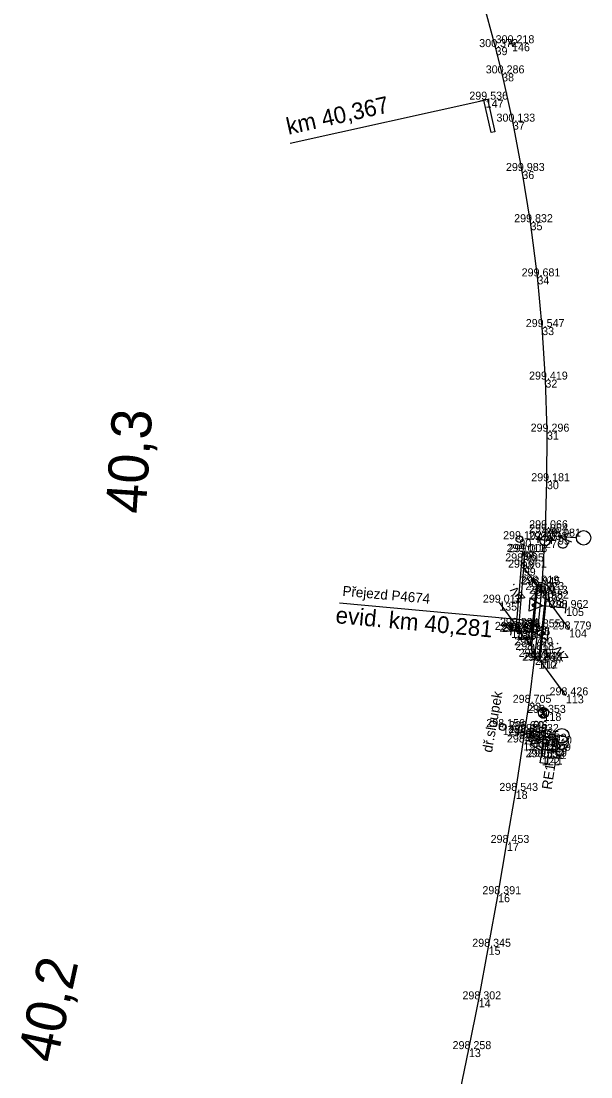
# Model space of a CAD drawing. Extents: x -684938 to -684389, y -1007777 to -1006471.
# Drawn here: x -684554.8 to -684469.4, y -1007124.9 to -1006966.7 of the extents above; entities that cross this region are included whole.
import ezdxf

# ---------------------------------------------------------------- set-up
doc = ezdxf.new("R2010")
doc.units = 0
for name, color, linetype in [('Vrstva 1', 7, 'Continuous'), ('Vrstva 12', 7, 'Continuous'), ('Vrstva 13', 7, 'Continuous'), ('Vrstva 25', 7, 'Continuous'), ('Vrstva 3', 7, 'Continuous'), ('Vrstva 33', 7, 'Continuous'), ('Vrstva 4', 7, 'Continuous'), ('Vrstva 43', 7, 'Continuous'), ('Vrstva 50', 7, 'Continuous'), ('Vrstva 51', 7, 'Continuous'), ('Vrstva 60', 7, 'Continuous'), ('Vrstva 61', 7, 'Continuous'), ('Vrstva 63', 7, 'Continuous'), ('Vrstva 7', 7, 'Continuous'), ('Vrstva 9', 7, 'Continuous')]:
    doc.layers.add(name, color=color, linetype=linetype)

msp = doc.modelspace()

# ---------------------------------------------------------------- linework, layer by layer
at = {"layer": 'Vrstva 1'}
msp.add_lwpolyline([(-684489.29, -1007128.53), (-684487.68, -1007120.78), (-684486.2, -1007113.32), (-684484.73, -1007105.44), (-684483.31, -1007097.56), (-684481.98, -1007089.88), (-684480.67, -1007082.08), (-684479.54, -1007074.82), (-684479.4, -1007073.91), (-684479.32, -1007073.39), (-684479.23, -1007072.83), (-684478.66, -1007068.88), (-684477.78, -1007061.99), (-684477.29, -1007057.57), (-684476.77, -1007051.98), (-684476.28, -1007044.49), (-684476.22, -1007043.32), (-684476.19, -1007042.72), (-684475.99, -1007035.67), (-684475.98, -1007028.24), (-684476.22, -1007020.44), (-684476.71, -1007012.57), (-684477.42, -1007004.97), (-684478.45, -1006996.85), (-684479.68, -1006989.18), (-684481.1, -1006981.78), (-684482.71, -1006974.55), (-684483.69, -1006970.61), (-684485.64, -1006963.4)], dxfattribs=at)
at = {"layer": 'Vrstva 12'}
msp.add_line((-684476.74, -1007077.05), (-684476.39, -1007074.71), dxfattribs=at)
at = {"layer": 'Vrstva 13'}
msp.add_lwpolyline([(-684480.63, -1007058.2), (-684480.27, -1007058.25)], dxfattribs=at)
at = {"layer": 'Vrstva 25'}
for points in [[(-684475.99, -1007078), (-684476.98, -1007077.85), (-684476.67, -1007075.87), (-684475.69, -1007076.03), (-684475.99, -1007078)], [(-684475.4, -1007077.12), (-684476.39, -1007076.97), (-684476.08, -1007074.99), (-684475.09, -1007075.15), (-684475.4, -1007077.12)]]:
    msp.add_lwpolyline(points, dxfattribs=at)
at = {"layer": 'Vrstva 3'}
for p, q in [((-684477.31, -1007044.92), (-684477.24, -1007043.92)), ((-684475.31, -1007045.05), (-684475.24, -1007044.06)), ((-684474.33, -1007043.97), (-684471.58, -1007044.1)), ((-684477.27, -1007044.42), (-684475.28, -1007044.55)), ((-684480.39, -1007073.73), (-684480.24, -1007072.74)), ((-684480.31, -1007073.24), (-684478.33, -1007073.53)), ((-684478.41, -1007074.03), (-684478.26, -1007073.04)), ((-684477.67, -1007074.23), (-684474.94, -1007074.64)), ((-684477.56, -1007073.25), (-684474.83, -1007073.65))]:
    msp.add_line(p, q, dxfattribs=at)
for points in [[(-684472.23, -1007043.37), (-684474.33, -1007043.97), (-684472.3, -1007044.75)], [(-684475.41, -1007072.87), (-684477.56, -1007073.25), (-684475.61, -1007074.23)], [(-684475.52, -1007073.86), (-684477.67, -1007074.23), (-684475.72, -1007075.22)]]:
    msp.add_lwpolyline(points, dxfattribs=at)
for centre in [(-684470.49, -1007044.15), (-684473.75, -1007073.81), (-684473.87, -1007074.81)]:
    msp.add_circle(centre, 1.08, dxfattribs=at)
at = {"layer": 'Vrstva 33'}
for p, q in [((-684476.17, -1007075.48), (-684476.02, -1007074.49)), ((-684476.09, -1007074.99), (-684475.11, -1007075.14))]:
    msp.add_line(p, q, dxfattribs=at)
msp.add_lwpolyline([(-684476.74, -1007075.9), (-684476.44, -1007073.93), (-684474.46, -1007074.22), (-684474.76, -1007076.2), (-684476.74, -1007075.9)], dxfattribs=at)
at = {"layer": 'Vrstva 4'}
for p, q in [((-684507.07, -1007053.89), (-684477.2, -1007056.65)), ((-684477.79, -1007054.44), (-684478.1, -1007054.07)), ((-684473.19, -1007055.45), (-684473.04, -1007053.9)), ((-684481.25, -1007057.18), (-684481.43, -1007058.72)), ((-684476.67, -1007058.26), (-684476.37, -1007058.65))]:
    msp.add_line(p, q, dxfattribs=at)
for points in [[(-684478.28, -1007060.96), (-684477.33, -1007051.23), (-684476.22, -1007052.54), (-684477.26, -1007062.58), (-684478.28, -1007060.96)], [(-684473.12, -1007054.67), (-684476.58, -1007054.35), (-684478.67, -1007055.15), (-684478.49, -1007053.16), (-684476.58, -1007054.35)], [(-684481.34, -1007057.95), (-684477.88, -1007058.33), (-684475.78, -1007057.58), (-684475.99, -1007059.56), (-684477.88, -1007058.33)]]:
    msp.add_lwpolyline(points, dxfattribs=at)
for centre in [(-684477.94, -1007054.25), (-684476.52, -1007058.45)]:
    msp.add_circle(centre, 0.248, dxfattribs=at)
at = {"layer": 'Vrstva 43'}
msp.add_lwpolyline([(-684480.27, -1007058.25), (-684479.46, -1007048.63), (-684479.3, -1007046.31), (-684479.66, -1007046.26), (-684479.78, -1007047.68), (-684480.58, -1007057.36), (-684480.63, -1007058.2), (-684480.27, -1007058.25)], dxfattribs=at)
at = {"layer": 'Vrstva 50'}
msp.add_line((-684482.62, -1007072.46), (-684482.63, -1007072.55), dxfattribs=at)
msp.add_circle((-684482.62, -1007072.51), 0.5, dxfattribs=at)
at = {"layer": 'Vrstva 51'}
for points in [[(-684483.14, -1007053.87), (-684480.58, -1007057.36), (-684480.21, -1007058.09), (-684478.44, -1007060.26), (-684477.49, -1007051.03), (-684479.46, -1007048.63)], [(-684473.15, -1007067.76), (-684477.02, -1007062.52), (-684476.07, -1007053.27), (-684472.68, -1007057.89)]]:
    msp.add_lwpolyline(points, dxfattribs=at)
at = {"layer": 'Vrstva 60'}
for p, q in [((-684481.22, -1006970.03), (-684481.22, -1006970.03)), ((-684483.69, -1006970.61), (-684483.69, -1006970.61)), ((-684482.71, -1006974.55), (-684482.71, -1006974.55)), ((-684485.17, -1006978.49), (-684485.17, -1006978.49)), ((-684481.1, -1006981.78), (-684481.1, -1006981.78)), ((-684479.68, -1006989.18), (-684479.68, -1006989.18)), ((-684478.45, -1006996.85), (-684478.45, -1006996.85)), ((-684477.42, -1007004.97), (-684477.42, -1007004.97)), ((-684476.71, -1007012.57), (-684476.71, -1007012.57)), ((-684476.22, -1007020.44), (-684476.22, -1007020.44)), ((-684475.98, -1007028.24), (-684475.98, -1007028.24)), ((-684475.99, -1007035.67), (-684475.99, -1007035.67)), ((-684476.19, -1007042.72), (-684476.19, -1007042.72)), ((-684480.12, -1007044.36), (-684480.12, -1007044.36)), ((-684476.22, -1007043.32), (-684476.22, -1007043.32)), ((-684474.33, -1007043.97), (-684474.33, -1007043.97)), ((-684476.28, -1007044.49), (-684476.28, -1007044.49)), ((-684479.66, -1007046.26), (-684479.66, -1007046.26)), ((-684479.3, -1007046.31), (-684479.3, -1007046.31)), ((-684479.78, -1007047.68), (-684479.78, -1007047.68)), ((-684479.46, -1007048.63), (-684479.46, -1007048.63)), ((-684477.49, -1007051.03), (-684477.49, -1007051.03)), ((-684477.33, -1007051.23), (-684477.33, -1007051.23)), ((-684476.77, -1007051.98), (-684476.77, -1007051.98)), ((-684483.14, -1007053.87), (-684483.14, -1007053.87)), ((-684476.22, -1007052.54), (-684476.22, -1007052.54)), ((-684476.07, -1007053.27), (-684476.07, -1007053.27)), ((-684473.12, -1007054.67), (-684473.12, -1007054.67)), ((-684481.34, -1007057.95), (-684481.34, -1007057.95)), ((-684480.63, -1007058.2), (-684480.63, -1007058.2)), ((-684480.58, -1007057.36), (-684480.58, -1007057.36)), ((-684480.27, -1007058.25), (-684480.27, -1007058.25)), ((-684480.21, -1007058.09), (-684480.21, -1007058.09)), ((-684477.29, -1007057.57), (-684477.29, -1007057.57)), ((-684472.68, -1007057.89), (-684472.68, -1007057.89)), ((-684478.44, -1007060.26), (-684478.44, -1007060.26)), ((-684478.28, -1007060.96), (-684478.28, -1007060.96)), ((-684477.78, -1007061.99), (-684477.78, -1007061.99)), ((-684477.26, -1007062.58), (-684477.26, -1007062.58)), ((-684477.02, -1007062.52), (-684477.02, -1007062.52)), ((-684473.15, -1007067.76), (-684473.15, -1007067.76)), ((-684478.66, -1007068.88), (-684478.66, -1007068.88)), ((-684476.51, -1007070.39), (-684476.51, -1007070.39)), ((-684482.62, -1007072.51), (-684482.62, -1007072.51)), ((-684479.23, -1007072.83), (-684479.23, -1007072.83)), ((-684479.4, -1007073.91), (-684479.4, -1007073.91)), ((-684479.32, -1007073.39), (-684479.32, -1007073.39)), ((-684477.67, -1007074.23), (-684477.67, -1007074.23)), ((-684477.56, -1007073.25), (-684477.56, -1007073.25)), ((-684479.54, -1007074.82), (-684479.54, -1007074.82)), ((-684476.39, -1007074.71), (-684476.39, -1007074.71)), ((-684475.6, -1007075.06), (-684475.6, -1007075.06)), ((-684476.74, -1007077.05), (-684476.74, -1007077.05)), ((-684476.33, -1007076.94), (-684476.33, -1007076.94)), ((-684475.74, -1007076.06), (-684475.74, -1007076.06)), ((-684480.67, -1007082.08), (-684480.67, -1007082.08)), ((-684481.98, -1007089.88), (-684481.98, -1007089.88)), ((-684483.31, -1007097.56), (-684483.31, -1007097.56)), ((-684484.73, -1007105.44), (-684484.73, -1007105.44)), ((-684486.2, -1007113.32), (-684486.2, -1007113.32)), ((-684487.68, -1007120.78), (-684487.68, -1007120.78))]:
    msp.add_line(p, q, dxfattribs=at)
at = {"layer": 'Vrstva 63'}
for p, q in [((-684476.34, -1007070.26), (-684476.78, -1007069.67)), ((-684476.1, -1007070.08), (-684476.44, -1007069.63)), ((-684477.12, -1007070.84), (-684476.5, -1007070.39)), ((-684476.5, -1007070.39), (-684476.96, -1007069.78)), ((-684476.55, -1007071.15), (-684476.9, -1007070.68)), ((-684476.22, -1007071.1), (-684476.66, -1007070.5)), ((-684475.89, -1007069.93), (-684476.5, -1007070.39)), ((-684476.5, -1007070.39), (-684476.04, -1007071))]:
    msp.add_line(p, q, dxfattribs=at)
msp.add_circle((-684476.5, -1007070.39), 0.764, dxfattribs=at)
for start, end in [(36.8703, 126.7638), (216.4195, 306.7375)]:
    msp.add_arc((-684476.5, -1007070.39), 0.765, start, end, dxfattribs=at)
at = {"layer": 'Vrstva 7'}
for p, q in [((-684481.71, -1006970.15), (-684480.74, -1006969.91)), ((-684481.1, -1006970.51), (-684481.34, -1006969.54)), ((-684480.12, -1007044.41), (-684480.11, -1007044.31))]:
    msp.add_line(p, q, dxfattribs=at)
for centre, radius in [((-684480.12, -1007044.36), 0.5), ((-684476.28, -1007044.61), 0.75)]:
    msp.add_circle(centre, radius, dxfattribs=at)
at = {"layer": 'Vrstva 9'}
msp.add_line((-684514.45, -1006985.02), (-684485.17, -1006978.49), dxfattribs=at)
msp.add_lwpolyline([(-684486.05, -1006978.68), (-684485.46, -1006978.55), (-684484.88, -1006978.42), (-684483.79, -1006983.3), (-684484.37, -1006983.43), (-684485.46, -1006978.55)], dxfattribs=at)

# ---------------------------------------------------------------- texts
at = {"layer": 'Vrstva 25'}
for s, p in [('k.s.', (-684473.61, -1007077.46)), ('RE1', (-684475.3, -1007081.96))]:
    msp.add_text(s, height=1.5, rotation=81.1596, dxfattribs=at).set_placement(p)
at = {"layer": 'Vrstva 3'}
for s, rotation, p in [('C', 87.2947, (-684472.9, -1007045.9)), ('B', 81.817, (-684476.59, -1007072.87)), ('A', 81.512, (-684477.05, -1007076.01))]:
    msp.add_text(s, height=1.5, rotation=rotation, dxfattribs=at).set_placement(p)
at = {"layer": 'Vrstva 4'}
for s, height, p in [('Přejezd P4674', 1.5, (-684506.67, -1007052.83)), ('evid. km 40,281', 2.5, (-684507.74, -1007056.93))]:
    msp.add_text(s, height=height, rotation=354.7233, dxfattribs=at).set_placement(p)
at = {"layer": 'Vrstva 50'}
msp.add_text('dř.sloupek', height=1.5, rotation=80.1558, dxfattribs=at).set_placement((-684484.23, -1007076.41))
at = {"layer": 'Vrstva 51'}
for rotation, p in [(129.3777, (-684479.13, -1007053.2)), (126.4268, (-684472.69, -1007062.13))]:
    msp.add_text('živ.', height=1.5, rotation=rotation, dxfattribs=at).set_placement(p)
at = {"layer": 'Vrstva 60'}
for s, p in [('146', (-684481.22, -1006971.23)), ('39', (-684483.69, -1006971.81)), ('38', (-684482.71, -1006975.75)), ('147', (-684485.17, -1006979.69)), ('37', (-684481.1, -1006982.98)), ('36', (-684479.68, -1006990.38)), ('35', (-684478.45, -1006998.05)), ('34', (-684477.42, -1007006.17)), ('33', (-684476.71, -1007013.77)), ('32', (-684476.22, -1007021.64)), ('31', (-684475.98, -1007029.44)), ('30', (-684475.99, -1007036.86)), ('29', (-684476.19, -1007043.93)), ('90', (-684480.12, -1007045.56)), ('28', (-684476.22, -1007044.52)), ('95', (-684474.33, -1007045.17)), ('27', (-684476.28, -1007045.69)), ('97', (-684479.66, -1007047.46)), ('96', (-684479.3, -1007047.51)), ('98', (-684479.78, -1007048.88)), ('99', (-684479.46, -1007049.83)), ('100', (-684477.49, -1007052.23)), ('101', (-684477.33, -1007052.43)), ('26', (-684476.77, -1007053.18)), ('135', (-684483.14, -1007055.07)), ('102', (-684476.22, -1007053.74)), ('103', (-684476.07, -1007054.47)), ('105', (-684473.12, -1007055.87)), ('131', (-684481.34, -1007059.15)), ('130', (-684480.63, -1007059.4)), ('134', (-684480.58, -1007058.56)), ('129', (-684480.27, -1007059.45)), ('133', (-684480.21, -1007059.29)), ('25', (-684477.29, -1007058.77)), ('104', (-684472.68, -1007059.09)), ('132', (-684478.44, -1007061.46)), ('111', (-684478.28, -1007062.17)), ('24', (-684477.78, -1007063.19)), ('110', (-684477.26, -1007063.78)), ('112', (-684477.02, -1007063.72)), ('113', (-684473.15, -1007068.96)), ('23', (-684478.66, -1007070.08)), ('118', (-684476.51, -1007071.59)), ('124', (-684482.62, -1007073.71)), ('22', (-684479.23, -1007074.03)), ('20', (-684479.4, -1007075.11)), ('21', (-684479.32, -1007074.59)), ('120', (-684477.67, -1007075.44)), ('119', (-684477.56, -1007074.45)), ('19', (-684479.54, -1007076.02)), ('121', (-684476.39, -1007075.91)), ('123', (-684475.6, -1007076.26)), ('122', (-684476.74, -1007078.25)), ('141', (-684476.33, -1007078.14)), ('151', (-684475.74, -1007077.26)), ('18', (-684480.67, -1007083.28)), ('17', (-684481.98, -1007091.08)), ('16', (-684483.31, -1007098.76)), ('15', (-684484.73, -1007106.64)), ('14', (-684486.2, -1007114.52)), ('13', (-684487.68, -1007121.97))]:
    msp.add_text(s, height=1.2, dxfattribs=at).set_placement(p)
at = {"layer": 'Vrstva 61'}
for s, p in [('300.372', (-684486.14, -1006970.61)), ('300.218', (-684483.68, -1006970.03)), ('300.286', (-684485.16, -1006974.55)), ('299.536', (-684487.62, -1006978.49)), ('300.133', (-684483.55, -1006981.78)), ('299.983', (-684482.13, -1006989.18)), ('299.832', (-684480.9, -1006996.85)), ('299.681', (-684479.78, -1007004.97)), ('299.547', (-684479.16, -1007012.57)), ('299.419', (-684478.67, -1007020.44)), ('299.296', (-684478.43, -1007028.24)), ('299.181', (-684478.34, -1007035.67)), ('299.054', (-684478.67, -1007043.32)), ('299.066', (-684478.65, -1007042.72)), ('299.081', (-684476.69, -1007043.97)), ('299.102', (-684482.56, -1007044.36)), ('299.033', (-684478.73, -1007044.49)), ('299.011', (-684482.02, -1007046.26)), ('299.008', (-684481.75, -1007046.31)), ('298.995', (-684482.24, -1007047.68)), ('298.961', (-684481.82, -1007048.63)), ('298.919', (-684479.95, -1007051.03)), ('298.945', (-684479.79, -1007051.23)), ('298.923', (-684479.22, -1007051.98)), ('299.013', (-684478.68, -1007052.54)), ('298.982', (-684478.52, -1007053.27)), ('299.012', (-684485.59, -1007053.87)), ('298.962', (-684475.57, -1007054.67)), ('298.883', (-684483.79, -1007057.95)), ('298.894', (-684483.08, -1007058.2)), ('298.894', (-684483.03, -1007057.36)), ('298.893', (-684482.72, -1007058.25)), ('298.875', (-684482.67, -1007058.09)), ('298.855', (-684479.74, -1007057.57)), ('298.779', (-684475.13, -1007057.89)), ('298.790', (-684480.89, -1007060.26)), ('298.818', (-684480.73, -1007060.96)), ('298.795', (-684480.23, -1007061.99)), ('298.862', (-684479.7, -1007062.58)), ('298.848', (-684479.47, -1007062.52)), ('298.426', (-684475.6, -1007067.76)), ('298.705', (-684481.12, -1007068.88)), ('298.353', (-684478.96, -1007070.39)), ('298.156', (-684485.08, -1007072.51)), ('298.630', (-684481.85, -1007073.91)), ('298.630', (-684481.77, -1007073.39)), ('298.646', (-684481.68, -1007072.83)), ('298.632', (-684480.01, -1007073.25)), ('298.627', (-684481.99, -1007074.82)), ('298.595', (-684480.12, -1007074.23)), ('298.492', (-684478.84, -1007074.71)), ('299.470', (-684478.05, -1007075.06)), ('298.557', (-684479.19, -1007077.05)), ('299.769', (-684478.79, -1007076.94)), ('298.509', (-684478.2, -1007076.06)), ('298.543', (-684483.12, -1007082.08)), ('298.453', (-684484.43, -1007089.88)), ('298.391', (-684485.66, -1007097.56)), ('298.345', (-684487.18, -1007105.44)), ('298.302', (-684488.65, -1007113.32)), ('298.258', (-684490.13, -1007120.78))]:
    msp.add_text(s, height=1.2, dxfattribs=at).set_placement(p)
at = {"layer": 'Vrstva 7'}
for s, rotation, p in [('40,3', 86.2138, (-684536.15, -1007040.65)), ('40,2', 77.7139, (-684549.5, -1007123.04))]:
    msp.add_text(s, height=6, rotation=rotation, dxfattribs=at).set_placement(p)
at = {"layer": 'Vrstva 9'}
msp.add_text('km 40,367', height=2.5, rotation=12.5724, dxfattribs=at).set_placement((-684514.73, -1006983.76))

doc.saveas('drawing.dxf')
